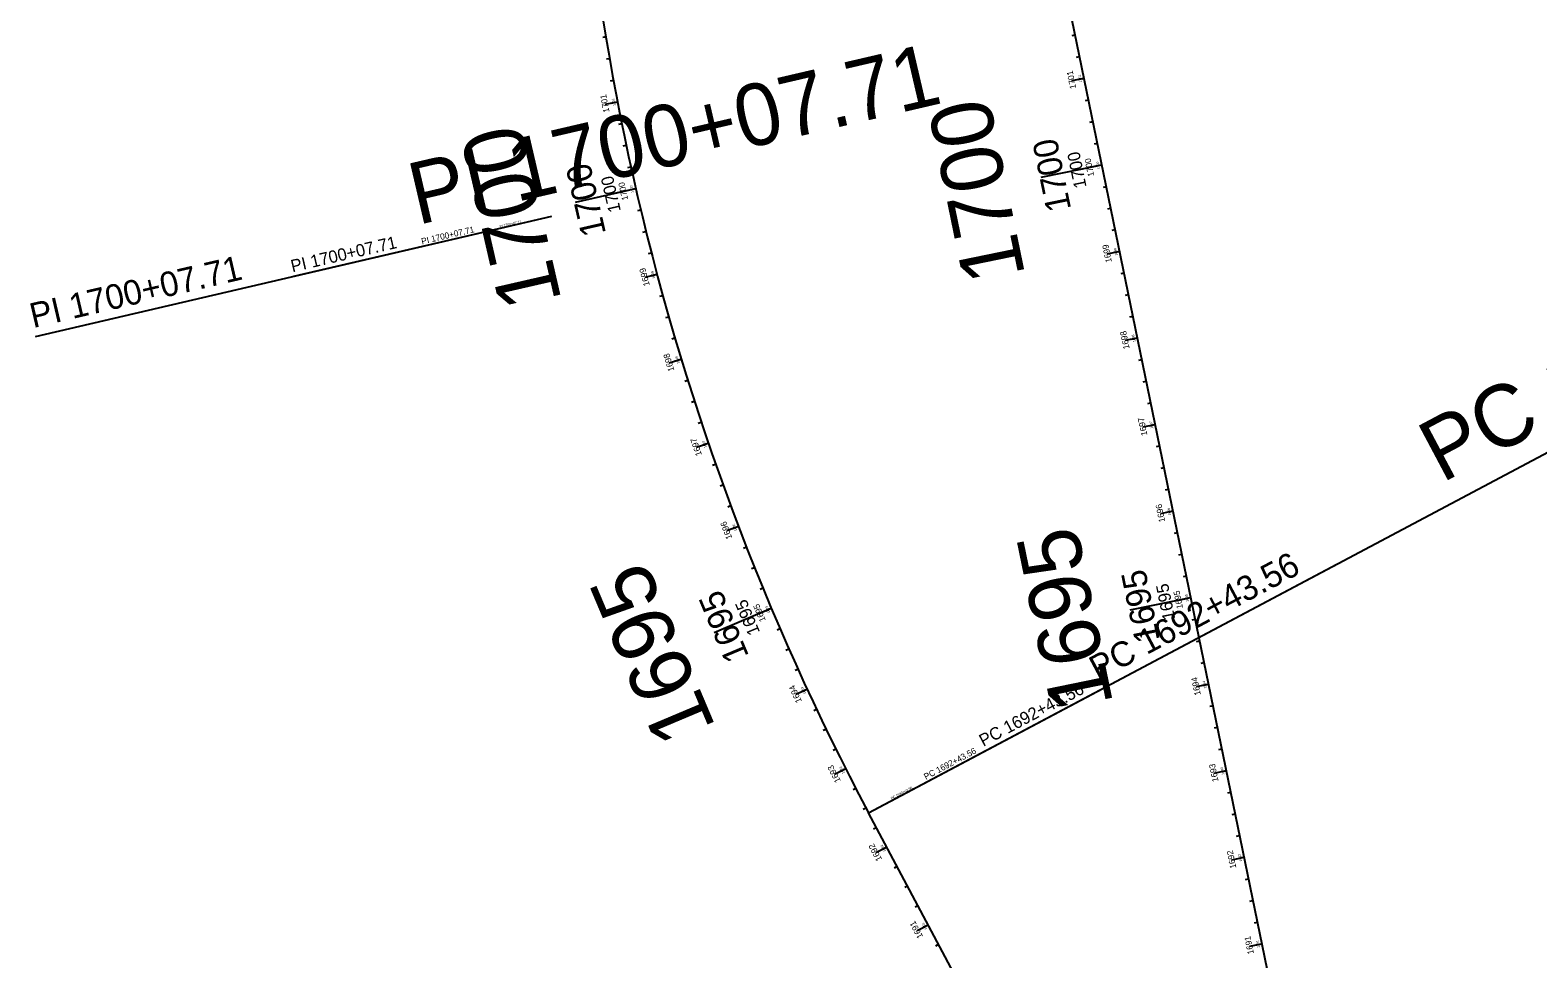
# Model space of a CAD drawing. Extents: x 353835 to 363333, y 126218 to 205387.
# Drawn here: x 360757 to 362463, y 128334 to 129386 of the extents above; entities that cross this region are included whole.
import ezdxf

# ---------------------------------------------------------------- set-up
doc = ezdxf.new("R2010")
doc.units = 0
for name, color, linetype in [('P_ALI_100_PIData', 7, 'Continuous'), ('P_ALI_100_Sta', 7, 'Continuous'), ('P_ALI_100_Tic', 7, 'Continuous'), ('P_ALI_20', 7, 'Continuous'), ('P_ALI_200_PIData', 7, 'Continuous'), ('P_ALI_200_Sta', 7, 'Continuous'), ('P_ALI_200_Tic', 7, 'Continuous'), ('P_ALI_20_PIData', 7, 'Continuous'), ('P_ALI_20_Sta', 7, 'Continuous'), ('P_ALI_20_Tic', 7, 'Continuous'), ('P_ALI_500_PIData', 7, 'Continuous'), ('P_ALI_500_Sta', 7, 'Continuous'), ('P_ALI_50_PIData', 7, 'Continuous'), ('P_ALI_50_Sta', 7, 'Continuous'), ('P_ALI_50_Tic', 7, 'Continuous')]:
    doc.layers.add(name, color=color, linetype=linetype)

msp = doc.modelspace()

# ---------------------------------------------------------------- linework, layer by layer
for points in [[(361949.7, 129331.2), (361949.7, 129331.2)], [(361989.9, 129135.3), (361989.9, 129135.3)], [(362010, 129037.3), (362010, 129037.3)], [(362030.1, 128939.3), (362030.1, 128939.3)], [(362050.2, 128841.4), (362050.2, 128841.4)], [(362090.4, 128645.5), (362090.4, 128645.5)], [(362110.5, 128547.5), (362110.5, 128547.5)], [(362130.6, 128449.6), (362130.6, 128449.6)], [(362150.7, 128351.6), (362150.8, 128351.6)]]:
    msp.add_lwpolyline(points)
at = {"layer": 'P_ALI_100_PIData'}
for points in [[(361347.3, 129174.5), (361055.2, 129106.6)], [(361347.3, 129174.5), (361288.9, 129160.9)], [(361705.9, 128499.7), (361970.8, 128640.5)], [(361705.9, 128499.7), (361758.9, 128527.9)]]:
    msp.add_lwpolyline(points, dxfattribs=at)
at = {"layer": 'P_ALI_100_Tic'}
for points in [[(361942.8, 129329.8), (361949.7, 129331.2)], [(361414.9, 129303), (361421.8, 129304.3)], [(361901.2, 129219.1), (361969.8, 129233.2)], [(361956.1, 129230.4), (361969.8, 129233.2)], [(361374.2, 129190.8), (361442.4, 129206.5)], [(361428.8, 129203.3), (361442.4, 129206.5)], [(361983, 129133.9), (361989.9, 129135.3)], [(361459.7, 129107.6), (361466.4, 129109.4)], [(362003.1, 129035.9), (362010, 129037.3)], [(361487.1, 129011.2), (361493.8, 129013.2)], [(362023.2, 128937.9), (362030.1, 128939.3)], [(361517.9, 128915.8), (361524.5, 128918.1)], [(362043.3, 128840), (362050.2, 128841.4)], [(361552, 128821.5), (361558.6, 128824)], [(362001.7, 128729.4), (362070.3, 128743.4)], [(362056.6, 128740.6), (362070.3, 128743.4)], [(361531.3, 128704), (361595.8, 128731.2)], [(361582.9, 128725.8), (361595.8, 128731.2)], [(361629.9, 128636.9), (361636.3, 128639.8)], [(362083.6, 128644.1), (362090.4, 128645.5)], [(361673.6, 128546.7), (361679.9, 128549.8)], [(362103.7, 128546.1), (362110.5, 128547.5)], [(361720.1, 128458), (361726.3, 128461.3)], [(362123.8, 128448.2), (362130.6, 128449.6)], [(361767, 128369.7), (361773.2, 128372.9)], [(362143.9, 128350.2), (362150.7, 128351.6)]]:
    msp.add_lwpolyline(points, dxfattribs=at)
at = {"layer": 'P_ALI_20'}
for p, q in [((362324.5, 127505.2), (361863.7, 129750.1)), ((362054.4, 127843.7), (361705.9, 128499.7))]:
    msp.add_line(p, q, dxfattribs=at)
msp.add_arc((364244.8, 129848.6), 2875, 178.2122, 207.9813, dxfattribs=at)
at = {"layer": 'P_ALI_200_PIData'}
for points in [[(361347.3, 129174.5), (360763, 129038.6)], [(361705.9, 128499.7), (362235.7, 128781.2)]]:
    msp.add_lwpolyline(points, dxfattribs=at)
at = {"layer": 'P_ALI_200_Tic'}
for points in [[(361935.9, 129328.4), (361949.7, 129331.2)], [(361408, 129301.7), (361421.8, 129304.3)], [(361942.3, 129227.6), (361969.8, 129233.2)], [(361415.1, 129200.2), (361442.4, 129206.5)], [(361976.2, 129132.4), (361989.9, 129135.3)], [(361452.9, 129105.8), (361466.4, 129109.4)], [(361996.3, 129034.5), (362010, 129037.3)], [(361480.4, 129009.2), (361493.8, 129013.2)], [(362016.4, 128936.5), (362030.1, 128939.3)], [(361511.3, 128913.5), (361524.5, 128918.1)], [(362036.5, 128838.6), (362050.2, 128841.4)], [(361545.5, 128819.1), (361558.6, 128824)], [(362042.9, 128737.8), (362070.3, 128743.4)], [(361570, 128720.4), (361595.8, 128731.2)], [(361623.6, 128633.9), (361636.3, 128639.8)], [(362076.7, 128642.7), (362090.4, 128645.5)], [(361667.4, 128543.5), (361679.9, 128549.8)], [(362096.8, 128544.7), (362110.5, 128547.5)], [(361713.9, 128454.7), (361726.3, 128461.3)], [(362116.9, 128446.7), (362130.6, 128449.6)], [(361760.9, 128366.4), (361773.2, 128372.9)], [(362137, 128348.8), (362150.7, 128351.6)]]:
    msp.add_lwpolyline(points, dxfattribs=at)
at = {"layer": 'P_ALI_20_Tic'}
for points in [[(361407.2, 129377.9), (361408.5, 129378.1)], [(361938.2, 129379.9), (361939.6, 129380.2)], [(361411.4, 129353.2), (361412.7, 129353.5)], [(361943.3, 129355.4), (361944.6, 129355.7)], [(361415.8, 129328.6), (361417.2, 129328.9)], [(361946.9, 129330.6), (361949.7, 129331.2)], [(361419, 129303.8), (361421.8, 129304.3)], [(361953.3, 129306.4), (361954.7, 129306.7)], [(361425.3, 129279.5), (361426.6, 129279.8)], [(361958.3, 129281.9), (361959.7, 129282.2)], [(361430.3, 129255), (361431.7, 129255.3)], [(361963.4, 129257.4), (361964.7, 129257.7)], [(361435.6, 129230.6), (361436.9, 129230.9)], [(361967, 129232.7), (361969.8, 129233.2)], [(361439.7, 129205.8), (361442.4, 129206.5)], [(361973.4, 129208.4), (361974.8, 129208.7)], [(361978.5, 129184), (361979.8, 129184.2)], [(361446.7, 129181.8), (361448.1, 129182.1)], [(361452.7, 129157.5), (361454, 129157.8)], [(361983.5, 129159.5), (361984.9, 129159.8)], [(361458.8, 129133.2), (361460.1, 129133.6)], [(361987.1, 129134.7), (361989.9, 129135.3)], [(361463.7, 129108.7), (361466.4, 129109.4)], [(361993.5, 129110.5), (361994.9, 129110.8)], [(361471.6, 129084.9), (361473, 129085.3)], [(361998.6, 129086), (361999.9, 129086.3)], [(361478.4, 129060.8), (361479.7, 129061.2)], [(362003.6, 129061.5), (362005, 129061.8)], [(361485.3, 129036.8), (361486.7, 129037.2)], [(362007.2, 129036.7), (362010, 129037.3)], [(361491.2, 129012.4), (361493.8, 129013.2)], [(362013.6, 129012.5), (362015, 129012.8)], [(361499.9, 128988.9), (361501.2, 128989.3)], [(362018.7, 128988), (362020, 128988.3)], [(361507.4, 128965.1), (361508.8, 128965.5)], [(362023.7, 128963.6), (362025.1, 128963.8)], [(361515.2, 128941.3), (361516.6, 128941.8)], [(362027.4, 128938.8), (362030.1, 128939.3)], [(361521.9, 128917.2), (361524.5, 128918.1)], [(362033.7, 128914.6), (362035.1, 128914.9)], [(361531.4, 128894), (361532.7, 128894.5)], [(362038.8, 128890.1), (362040.1, 128890.4)], [(361539.8, 128870.4), (361541.1, 128870.9)], [(362043.8, 128865.6), (362045.2, 128865.9)], [(361548.4, 128846.9), (361549.7, 128847.4)], [(362047.5, 128840.8), (362050.2, 128841.4)], [(361555.9, 128823), (361558.6, 128824)], [(362053.9, 128816.6), (362055.2, 128816.9)], [(361566.3, 128800.2), (361567.6, 128800.7)], [(362058.9, 128792.1), (362060.3, 128792.4)], [(361575.5, 128777), (361576.8, 128777.5)], [(362063.9, 128767.6), (362065.3, 128767.9)], [(361584.9, 128753.8), (361586.2, 128754.3)], [(362067.6, 128742.9), (362070.3, 128743.4)], [(361593.2, 128730.2), (361595.8, 128731.2)], [(361604.3, 128707.7), (361605.6, 128708.3)], [(362074, 128718.7), (362075.3, 128718.9)], [(362079, 128694.2), (362080.4, 128694.5)], [(361614.4, 128684.8), (361615.6, 128685.3)], [(361624.6, 128662), (361625.9, 128662.5)], [(362084, 128669.7), (362085.4, 128670)], [(361633.7, 128638.6), (361636.3, 128639.8)], [(362087.7, 128644.9), (362090.4, 128645.5)], [(362094.1, 128620.7), (362095.4, 128621)], [(361645.6, 128616.6), (361646.9, 128617.2)], [(361656.4, 128594), (361657.7, 128594.6)], [(362099.1, 128596.2), (362100.5, 128596.5)], [(361667.4, 128571.5), (361668.7, 128572.2)], [(362104.1, 128571.7), (362105.5, 128572)], [(361677.4, 128548.6), (361679.9, 128549.8)], [(362107.8, 128547), (362110.5, 128547.5)], [(361690, 128526.9), (361691.3, 128527.6)], [(362114.2, 128522.7), (362115.6, 128523)], [(361701.6, 128504.8), (361702.9, 128505.4)], [(361713.3, 128482.7), (361714.6, 128483.3)], [(362119.2, 128498.3), (362120.6, 128498.5)], [(362124.2, 128473.8), (362125.6, 128474)], [(361723.8, 128459.9), (361726.3, 128461.3)], [(362127.9, 128449), (362130.6, 128449.6)], [(361736.8, 128438.5), (361738, 128439.2)], [(361748.5, 128416.4), (361749.8, 128417.1)], [(362134.3, 128424.8), (362135.7, 128425.1)], [(362139.3, 128400.3), (362140.7, 128400.6)], [(361760.3, 128394.4), (361761.5, 128395)], [(361770.8, 128371.6), (361773.2, 128372.9)], [(362144.3, 128375.8), (362145.7, 128376.1)], [(361783.7, 128350.2), (361785, 128350.9)], [(362148, 128351), (362150.7, 128351.6)]]:
    msp.add_lwpolyline(points, dxfattribs=at)
at = {"layer": 'P_ALI_500_PIData'}
for points in [[(361705.9, 128499.7), (363030.5, 129203.5)], [(361347.3, 129174.5), (361201.2, 129140.6)]]:
    msp.add_lwpolyline(points, dxfattribs=at)
at = {"layer": 'P_ALI_50_PIData'}
for points in [[(361347.3, 129174.5), (361201.2, 129140.6)], [(361347.3, 129174.5), (361201.2, 129140.6)], [(361705.9, 128499.7), (361838.3, 128570.1)], [(361705.9, 128499.7), (361838.3, 128570.1)]]:
    msp.add_lwpolyline(points, dxfattribs=at)
at = {"layer": 'P_ALI_50_Tic'}
for points in [[(361405.1, 129377.6), (361408.5, 129378.1)], [(361405.1, 129377.6), (361408.5, 129378.1)], [(361936.2, 129379.5), (361939.6, 129380.2)], [(361409.3, 129352.9), (361412.7, 129353.5)], [(361409.3, 129352.9), (361412.7, 129353.5)], [(361941.2, 129355), (361944.6, 129355.7)], [(361413.7, 129328.3), (361417.2, 129328.9)], [(361413.7, 129328.3), (361417.2, 129328.9)], [(361942.8, 129329.8), (361949.7, 129331.2)], [(361414.9, 129303), (361421.8, 129304.3)], [(361414.9, 129303), (361421.8, 129304.3)], [(361951.3, 129306), (361954.7, 129306.7)], [(361423.2, 129279.1), (361426.6, 129279.8)], [(361423.2, 129279.1), (361426.6, 129279.8)], [(361956.3, 129281.5), (361959.7, 129282.2)], [(361428.3, 129254.6), (361431.7, 129255.3)], [(361428.3, 129254.6), (361431.7, 129255.3)], [(361961.3, 129257), (361964.7, 129257.7)], [(361433.5, 129230.1), (361436.9, 129230.9)], [(361433.5, 129230.1), (361436.9, 129230.9)], [(361962.9, 129231.8), (361969.8, 129233.2)], [(361435.6, 129204.9), (361442.4, 129206.5)], [(361435.6, 129204.9), (361442.4, 129206.5)], [(361971.4, 129208), (361974.8, 129208.7)], [(361976.4, 129183.5), (361979.8, 129184.2)], [(361444.7, 129181.3), (361448.1, 129182.1)], [(361444.7, 129181.3), (361448.1, 129182.1)], [(361450.6, 129157), (361454, 129157.8)], [(361450.6, 129157), (361454, 129157.8)], [(361981.4, 129159), (361984.9, 129159.8)], [(361456.7, 129132.7), (361460.1, 129133.6)], [(361456.7, 129132.7), (361460.1, 129133.6)], [(361983, 129133.9), (361989.9, 129135.3)], [(361459.7, 129107.6), (361466.4, 129109.4)], [(361459.7, 129107.6), (361466.4, 129109.4)], [(361991.5, 129110.1), (361994.9, 129110.8)], [(361469.6, 129084.3), (361473, 129085.3)], [(361469.6, 129084.3), (361473, 129085.3)], [(361996.5, 129085.6), (361999.9, 129086.3)], [(361476.4, 129060.2), (361479.7, 129061.2)], [(361476.4, 129060.2), (361479.7, 129061.2)], [(362001.5, 129061.1), (362005, 129061.8)], [(361483.3, 129036.2), (361486.7, 129037.2)], [(361483.3, 129036.2), (361486.7, 129037.2)], [(362003.1, 129035.9), (362010, 129037.3)], [(361487.1, 129011.2), (361493.8, 129013.2)], [(361487.1, 129011.2), (361493.8, 129013.2)], [(362011.6, 129012.1), (362015, 129012.8)], [(361497.9, 128988.3), (361501.2, 128989.3)], [(361497.9, 128988.3), (361501.2, 128989.3)], [(362016.6, 128987.6), (362020, 128988.3)], [(361505.4, 128964.4), (361508.8, 128965.5)], [(361505.4, 128964.4), (361508.8, 128965.5)], [(362021.6, 128963.1), (362025.1, 128963.8)], [(361513.2, 128940.7), (361516.6, 128941.8)], [(361513.2, 128940.7), (361516.6, 128941.8)], [(362023.2, 128937.9), (362030.1, 128939.3)], [(361517.9, 128915.8), (361524.5, 128918.1)], [(361517.9, 128915.8), (361524.5, 128918.1)], [(362031.7, 128914.2), (362035.1, 128914.9)], [(361529.4, 128893.3), (361532.7, 128894.5)], [(361529.4, 128893.3), (361532.7, 128894.5)], [(362036.7, 128889.7), (362040.1, 128890.4)], [(361537.9, 128869.7), (361541.1, 128870.9)], [(361537.9, 128869.7), (361541.1, 128870.9)], [(362041.7, 128865.2), (362045.2, 128865.9)], [(361546.5, 128846.2), (361549.7, 128847.4)], [(361546.5, 128846.2), (361549.7, 128847.4)], [(362043.3, 128840), (362050.2, 128841.4)], [(361552, 128821.5), (361558.6, 128824)], [(361552, 128821.5), (361558.6, 128824)], [(362051.8, 128816.2), (362055.2, 128816.9)], [(361564.3, 128799.4), (361567.6, 128800.7)], [(361564.3, 128799.4), (361567.6, 128800.7)], [(362056.8, 128791.7), (362060.3, 128792.4)], [(361573.5, 128776.2), (361576.8, 128777.5)], [(361573.5, 128776.2), (361576.8, 128777.5)], [(362061.9, 128767.2), (362065.3, 128767.9)], [(361583, 128753), (361586.2, 128754.3)], [(361583, 128753), (361586.2, 128754.3)], [(362063.5, 128742), (362070.3, 128743.4)], [(361589.4, 128728.5), (361595.8, 128731.2)], [(361589.4, 128728.5), (361595.8, 128731.2)], [(361602.4, 128706.9), (361605.6, 128708.3)], [(361602.4, 128706.9), (361605.6, 128708.3)], [(362071.9, 128718.2), (362075.3, 128718.9)], [(362076.9, 128693.7), (362080.4, 128694.5)], [(361612.4, 128683.9), (361615.6, 128685.3)], [(361612.4, 128683.9), (361615.6, 128685.3)], [(361622.7, 128661.1), (361625.9, 128662.5)], [(361622.7, 128661.1), (361625.9, 128662.5)], [(362082, 128669.3), (362085.4, 128670)], [(361629.9, 128636.9), (361636.3, 128639.8)], [(361629.9, 128636.9), (361636.3, 128639.8)], [(362083.6, 128644.1), (362090.4, 128645.5)], [(362092, 128620.3), (362095.4, 128621)], [(361643.7, 128615.7), (361646.9, 128617.2)], [(361643.7, 128615.7), (361646.9, 128617.2)], [(361654.5, 128593.1), (361657.7, 128594.6)], [(361654.5, 128593.1), (361657.7, 128594.6)], [(362097, 128595.8), (362100.5, 128596.5)], [(361665.6, 128570.6), (361668.7, 128572.2)], [(361665.6, 128570.6), (361668.7, 128572.2)], [(362102.1, 128571.3), (362105.5, 128572)], [(361673.6, 128546.7), (361679.9, 128549.8)], [(361673.6, 128546.7), (361679.9, 128549.8)], [(362103.7, 128546.1), (362110.5, 128547.5)], [(361688.2, 128526), (361691.3, 128527.6)], [(361688.2, 128526), (361691.3, 128527.6)], [(362112.1, 128522.3), (362115.6, 128523)], [(361699.8, 128503.8), (361702.9, 128505.4)], [(361699.8, 128503.8), (361702.9, 128505.4)], [(361711.5, 128481.7), (361714.6, 128483.3)], [(361711.5, 128481.7), (361714.6, 128483.3)], [(362117.2, 128497.8), (362120.6, 128498.5)], [(362122.2, 128473.3), (362125.6, 128474)], [(361720.1, 128458), (361726.3, 128461.3)], [(361720.1, 128458), (361726.3, 128461.3)], [(362123.8, 128448.2), (362130.6, 128449.6)], [(361735, 128437.5), (361738, 128439.2)], [(361735, 128437.5), (361738, 128439.2)], [(361746.7, 128415.5), (361749.8, 128417.1)], [(361746.7, 128415.5), (361749.8, 128417.1)], [(362132.2, 128424.4), (362135.7, 128425.1)], [(362137.3, 128399.9), (362140.7, 128400.6)], [(361758.4, 128393.4), (361761.5, 128395)], [(361758.4, 128393.4), (361761.5, 128395)], [(361767, 128369.7), (361773.2, 128372.9)], [(361767, 128369.7), (361773.2, 128372.9)], [(362142.3, 128375.4), (362145.7, 128376.1)], [(361781.9, 128349.2), (361785, 128350.9)], [(361781.9, 128349.2), (361785, 128350.9)], [(362143.9, 128350.2), (362150.7, 128351.6)]]:
    msp.add_lwpolyline(points, dxfattribs=at)

# ---------------------------------------------------------------- texts
at = {"layer": 'P_ALI_100_PIData'}
for s, rotation, p in [('PI 1700+07.71', 13.0967, (361054, 129111.4)), ('PC 1692+43.56', 27.9813, (361835.6, 128574.3))]:
    msp.add_text(s, height=14, rotation=rotation, dxfattribs=at).set_placement(p)
at = {"layer": 'P_ALI_100_Sta'}
for s, rotation, p in [('1700', 101.6001, (361952.5, 129208.2)), ('1700', 102.9063, (361425.7, 129181)), ('1695', 101.6001, (362052.8, 128719.4)), ('1695', 112.8708, (361583.3, 128704.2))]:
    msp.add_text(s, height=14, rotation=rotation, dxfattribs=at).set_placement(p)
at = {"layer": 'P_ALI_200_PIData'}
for s, rotation, p in [('PI 1700+07.71', 13.0967, (360760.7, 129048.3)), ('PC 1692+43.56', 27.9813, (361965.3, 128648.9))]:
    msp.add_text(s, height=28, rotation=rotation, dxfattribs=at).set_placement(p)
at = {"layer": 'P_ALI_200_Sta'}
for s, rotation, p in [('1700', 101.6001, (361935.1, 129183.1)), ('1700', 102.9063, (361408.9, 129155.6)), ('1695', 101.6001, (362035.3, 128695.3)), ('1695', 112.8708, (361570.9, 128677.2))]:
    msp.add_text(s, height=28, rotation=rotation, dxfattribs=at).set_placement(p)
at = {"layer": 'P_ALI_20_PIData'}
for s, rotation, p in [('PI 1700+07.71', 13.0967, (361288.7, 129161.9)), ('PC 1692+43.56', 27.9813, (361731.8, 128514.6))]:
    msp.add_text(s, height=2.8, rotation=rotation, dxfattribs=at).set_placement(p)
at = {"layer": 'P_ALI_20_Sta'}
for s, rotation, p in [('1701', 101.6001, (361947.4, 129326.9)), ('1701', 100.9134, (361419.5, 129300.1)), ('1700', 101.6001, (361967.6, 129228.5)), ('1700', 102.9063, (361440.4, 129201.7)), ('1699', 101.6001, (361987.7, 129130.7)), ('1699', 104.8992, (361464.5, 129104.7)), ('1698', 101.6001, (362007.8, 129032.8)), ('1698', 106.8921, (361492.1, 129008.5)), ('1697', 101.6001, (362027.9, 128934.8)), ('1697', 108.885, (361522.9, 128913.3)), ('1696', 101.6001, (362048, 128836.8)), ('1696', 110.8779, (361557.1, 128819.2)), ('1695', 101.6001, (362068.1, 128738.9)), ('1695', 112.8708, (361594.5, 128726.3)), ('1694', 114.8637, (361635.2, 128634.9)), ('1694', 101.6001, (362088.2, 128640.9)), ('1693', 116.8566, (361678.9, 128544.8)), ('1693', 101.6001, (362108.3, 128543)), ('1692', 117.9813, (361725.5, 128456.3)), ('1692', 101.6001, (362128.4, 128445)), ('1691', 117.9813, (361772.2, 128368.3)), ('1691', 101.6001, (362148.5, 128347.4))]:
    msp.add_text(s, height=2.8, rotation=rotation, dxfattribs=at).set_placement(p)
at = {"layer": 'P_ALI_500_PIData'}
for s, rotation, p in [('PI 1700+07.71', 13.0967, (361195.6, 129164.9)), ('PC 1692+43.56', 27.9813, (362354.4, 128872.6))]:
    msp.add_text(s, height=70, rotation=rotation, dxfattribs=at).set_placement(p)
at = {"layer": 'P_ALI_500_Sta'}
for s, rotation, p in [('1700', 101.6001, (361883.2, 129108)), ('1700', 102.9063, (361358.7, 129079.3)), ('1695', 101.6001, (361982.7, 128623)), ('1695', 112.8708, (361533.4, 128596.1))]:
    msp.add_text(s, height=70, rotation=rotation, dxfattribs=at).set_placement(p)
at = {"layer": 'P_ALI_50_PIData'}
for s, rotation, p in [('PI 1700+07.71', 13.0967, (361200.7, 129143)), ('PI 1700+07.71', 13.0967, (361200.7, 129143)), ('PC 1692+43.56', 27.9813, (361770.7, 128537)), ('PC 1692+43.56', 27.9813, (361770.7, 128537))]:
    msp.add_text(s, height=7, rotation=rotation, dxfattribs=at).set_placement(p)
at = {"layer": 'P_ALI_50_Sta'}
for s, rotation, p in [('1701', 101.6001, (361940.8, 129319.8)), ('1701', 100.9134, (361412.8, 129293)), ('1701', 100.9134, (361412.8, 129293)), ('1700', 101.6001, (361961.1, 129220.7)), ('1700', 102.9063, (361434, 129193.8)), ('1700', 102.9063, (361434, 129193.8)), ('1699', 101.6001, (361981.1, 129123.2)), ('1699', 104.8992, (361458.4, 129096.9)), ('1699', 104.8992, (361458.4, 129096.9)), ('1698', 101.6001, (362001.2, 129025.3)), ('1698', 106.8921, (361486.2, 129000.4)), ('1698', 106.8921, (361486.2, 129000.4)), ('1697', 101.6001, (362021.3, 128927.3)), ('1697', 108.885, (361517.4, 128905)), ('1697', 108.885, (361517.4, 128905)), ('1696', 101.6001, (362041.4, 128829.4)), ('1696', 110.8779, (361551.8, 128810.8)), ('1696', 110.8779, (361551.8, 128810.8)), ('1695', 101.6001, (362061.6, 128731.4)), ('1695', 112.8708, (361589.6, 128717.7)), ('1695', 112.8708, (361589.6, 128717.7)), ('1694', 114.8637, (361630.5, 128626.1)), ('1694', 114.8637, (361630.5, 128626.1)), ('1694', 101.6001, (362081.7, 128633.4)), ('1693', 116.8566, (361674.6, 128535.9)), ('1693', 116.8566, (361674.6, 128535.9)), ('1693', 101.6001, (362101.8, 128535.5)), ('1692', 117.9813, (361721.3, 128447.2)), ('1692', 117.9813, (361721.3, 128447.2)), ('1692', 101.6001, (362121.9, 128437.5)), ('1691', 117.9813, (361767.8, 128359.7)), ('1691', 117.9813, (361767.8, 128359.7)), ('1691', 101.6001, (362141.8, 128340.4))]:
    msp.add_text(s, height=7, rotation=rotation, dxfattribs=at).set_placement(p)

doc.saveas('drawing.dxf')
